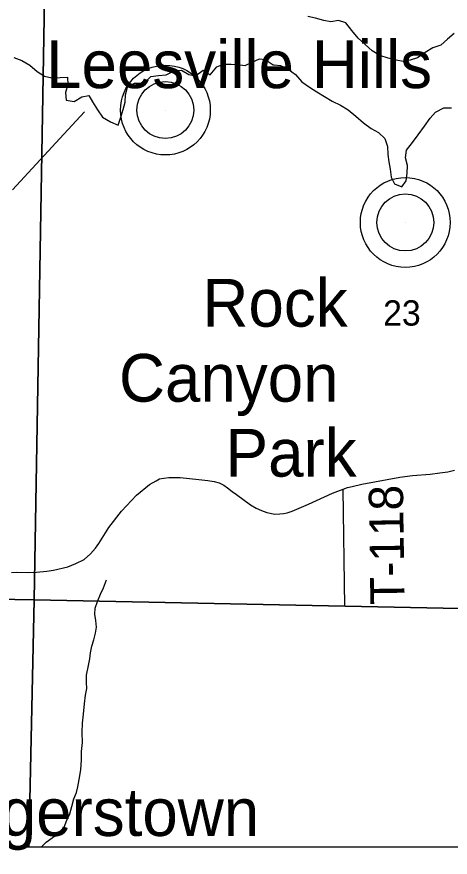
# Model space of a CAD drawing. Extents: x -1.2 to 34, y -8.5 to 22.
# Drawn here: x 7.31 to 8.028, y 18.307 to 19.699 of the extents above; entities that cross this region are included whole.
import ezdxf

# ---------------------------------------------------------------- set-up
doc = ezdxf.new("R2010")
doc.units = 0
for name, color, linetype in [('GM_X_County_Road', 7, 'Continuous'), ('GM_X_Major_Lake', 7, 'Continuous'), ('GM_X_Minor_River', 7, 'Continuous'), ('GM_X_Section', 7, 'Continuous'), ('GM_X_Section_Text', 7, 'Continuous'), ('GM_X_State_Route', 7, 'Continuous'), ('GM_X_Township_Road', 7, 'Continuous'), ('GM_X_Township_Road_Text', 7, 'Continuous'), ('GM_X_Unincorporated', 7, 'Continuous'), ('GM_X_Unincorporated_Location', 7, 'Continuous'), ('GM_X_Unincorporated_Text', 7, 'Continuous'), ('SH_Text', 7, 'Continuous')]:
    doc.layers.add(name, color=color, linetype=linetype)

msp = doc.modelspace()

# ---------------------------------------------------------------- linework, layer by layer
at = {"layer": 'GM_X_County_Road'}
msp.add_line((7.388, 19.5045), (7.4222, 19.5416), dxfattribs=at)
msp.add_lwpolyline([(7.303, 19.4125), (7.388, 19.5045)], dxfattribs=at)
at = {"layer": 'GM_X_Major_Lake'}
for points in [[(8.0348, 19.6713), (8.0239, 19.662), (8.0127, 19.6519), (7.9994, 19.6475), (7.987, 19.6397), (7.9742, 19.6312), (7.9621, 19.6272), (7.9504, 19.6247), (7.9386, 19.6272), (7.9256, 19.6304), (7.9118, 19.6347), (7.8992, 19.6428), (7.8872, 19.6529), (7.8756, 19.6633), (7.8655, 19.6764), (7.8554, 19.6891), (7.8432, 19.6927), (7.8303, 19.6906), (7.8189, 19.6927), (7.8051, 19.6966), (7.7922, 19.6995)], [(7.3052, 19.6314), (7.3182, 19.6263), (7.3316, 19.6186), (7.3439, 19.6082), (7.3559, 19.6004), (7.3681, 19.5976), (7.3817, 19.5985), (7.3939, 19.5987), (7.3945, 19.5866), (7.3909, 19.5737), (7.3919, 19.5608), (7.4048, 19.5587), (7.4176, 19.5665), (7.4294, 19.5686), (7.4356, 19.5581), (7.4435, 19.5446), (7.452, 19.5329), (7.4651, 19.5252), (7.4781, 19.5197), (7.4821, 19.5327), (7.486, 19.5453), (7.4896, 19.5575), (7.4902, 19.5696), (7.4934, 19.5826), (7.5051, 19.5888), (7.5207, 19.5891), (7.5319, 19.6003), (7.5448, 19.6016), (7.5573, 19.603), (7.5716, 19.61), (7.583, 19.6106), (7.5953, 19.6032), (7.6064, 19.6011), (7.6188, 19.6104), (7.6303, 19.6027), (7.6415, 19.6158), (7.6528, 19.6205), (7.6653, 19.6207), (7.6756, 19.6197), (7.6886, 19.6184), (7.6999, 19.6239), (7.712, 19.6291), (7.7215, 19.6281), (7.7346, 19.6192)], [(7.7346, 19.6192), (7.7368, 19.6196), (7.7471, 19.6183), (7.7598, 19.6124), (7.7717, 19.6035), (7.7825, 19.5912), (7.7952, 19.5823), (7.8075, 19.5749), (7.8198, 19.5671), (7.8329, 19.559), (7.8463, 19.5528), (7.8593, 19.545), (7.8717, 19.5346), (7.8848, 19.5231), (7.8971, 19.5142), (7.9094, 19.5072), (7.9202, 19.4975), (7.9242, 19.4843), (7.9252, 19.471), (7.9265, 19.4589), (7.929, 19.4468), (7.9304, 19.4335), (7.9359, 19.4222), (7.9481, 19.4175), (7.9556, 19.4271), (7.9569, 19.4397), (7.9578, 19.4526), (7.9542, 19.4654), (7.9559, 19.478), (7.9659, 19.4907), (7.9752, 19.5037), (7.9856, 19.5179), (7.9949, 19.531), (8.0039, 19.541), (8.0178, 19.5484), (8.0307, 19.5483)]]:
    msp.add_lwpolyline(points, dxfattribs=at)
at = {"layer": 'GM_X_Minor_River'}
for points in [[(7.416, 18.4521), (7.417, 18.4688), (7.4172, 18.4821), (7.4186, 18.4973), (7.4181, 18.514), (7.4187, 18.5292), (7.4198, 18.5391), (7.4208, 18.5497), (7.4219, 18.5615), (7.424, 18.5755), (7.4258, 18.5866), (7.4254, 18.5968), (7.4253, 18.6086), (7.4289, 18.6249), (7.4311, 18.6356), (7.4322, 18.6455), (7.4344, 18.6569), (7.4377, 18.6671), (7.4402, 18.6782), (7.4421, 18.6884), (7.4408, 18.6994), (7.4392, 18.71), (7.4399, 18.7199), (7.4436, 18.731), (7.4488, 18.7431), (7.4537, 18.7534), (7.4585, 18.7664)], [(7.3511, 18.3243), (7.3585, 18.3324), (7.3687, 18.3393), (7.38, 18.3463), (7.3883, 18.357), (7.3931, 18.3684), (7.398, 18.3791), (7.4013, 18.3913), (7.4046, 18.4042), (7.4087, 18.4145), (7.4109, 18.424), (7.4134, 18.4358), (7.416, 18.4521)]]:
    msp.add_lwpolyline(points, dxfattribs=at)
at = {"layer": 'GM_X_Section'}
for points in [[(6.3436, 19.7459), (7.3559, 19.7295), (7.3389, 18.7336), (6.3194, 18.751)], [(8.3845, 19.7092), (8.3694, 18.7126), (7.3389, 18.7336), (7.3559, 19.7295)]]:
    msp.add_lwpolyline(points, close=True, dxfattribs=at)
for points in [[(6.5688, 17.7257), (6.3024, 17.731), (6.3194, 18.751), (7.3389, 18.7336), (7.3297, 18.3243)], [(7.3297, 18.3243), (7.3389, 18.7336), (8.3694, 18.7126), (8.3383, 17.696), (7.3158, 17.711), (7.3184, 17.8243)]]:
    msp.add_lwpolyline(points, dxfattribs=at)
at = {"layer": 'GM_X_State_Route'}
msp.add_lwpolyline([(7.3012, 18.779), (7.3102, 18.7793), (7.3292, 18.779), (7.3428, 18.7792), (7.3598, 18.7807), (7.371, 18.7826), (7.3947, 18.7879), (7.4077, 18.7934), (7.4217, 18.8005), (7.4323, 18.8097), (7.4403, 18.8192), (7.4459, 18.8268), (7.4626, 18.8533), (7.4832, 18.8805), (7.5085, 18.9068), (7.5298, 18.9247), (7.5408, 18.9308), (7.5464, 18.9337), (7.5535, 18.935), (7.562, 18.936), (7.5806, 18.9358), (7.6115, 18.9327), (7.6265, 18.9309), (7.6368, 18.9293), (7.6451, 18.927), (7.6531, 18.9233), (7.6594, 18.9188), (7.6667, 18.9131), (7.674, 18.9077), (7.6972, 18.8909), (7.7068, 18.8852), (7.7156, 18.8814), (7.7244, 18.8782), (7.7378, 18.8756), (7.746, 18.8758), (7.7519, 18.8763), (7.7583, 18.8777), (7.7661, 18.8805), (7.7933, 18.8921), (7.8332, 18.9099), (7.8508, 18.9169), (7.8582, 18.9194), (7.8656, 18.9214), (7.8819, 18.9249), (7.9448, 18.9365), (7.966, 18.9393), (7.9953, 18.9418), (8.0113, 18.9436), (8.0243, 18.9455), (8.0353, 18.9481)], dxfattribs=at)
at = {"layer": 'GM_X_Township_Road'}
msp.add_line((7.8536, 18.7226), (7.8508, 18.9169), dxfattribs=at)
at = {"layer": 'GM_X_Unincorporated'}
for centre, radius in [((7.5562, 19.5445), 0.0744), ((7.5562, 19.5445), 0.0472), ((7.9539, 19.3584), 0.0744), ((7.9539, 19.3584), 0.0472)]:
    msp.add_circle(centre, radius, dxfattribs=at)
at = {"layer": 'GM_X_Unincorporated_Location'}
for p, q in [((7.5562, 19.5445), (7.5562, 19.5445)), ((7.9539, 19.3584), (7.9539, 19.3584))]:
    msp.add_line(p, q, dxfattribs=at)
at = {"layer": 'SH_Text'}
msp.add_lwpolyline([(6.5732, 17.8243), (6.5732, 18.3243), (8.2113, 18.3243), (8.2113, 17.8243), (6.7063, 17.8243)], dxfattribs=at)

# ---------------------------------------------------------------- texts
at = {"layer": 'GM_X_Section_Text'}
msp.add_text('23', height=0.04186, rotation=0, dxfattribs=at).set_placement((7.9172, 19.1876))
at = {"layer": 'GM_X_Township_Road_Text'}
msp.add_text('T-118', height=0.05682, rotation=90.8431, dxfattribs=at).set_placement((7.9529, 18.7256))
at = {"layer": 'GM_X_Unincorporated_Text'}
for s, height, p in [('Leesville Hills', 0.078977, (7.3585, 19.5808)), ('Rock', 0.07898, (7.6176, 19.1858)), ('Canyon', 0.07898, (7.4793, 19.0616)), ('Park', 0.07898, (7.656, 18.9375)), ('New Hagerstown', 0.078977, (6.9076, 18.3425))]:
    msp.add_text(s, height=height, rotation=0, dxfattribs=at).set_placement(p)

doc.saveas('drawing.dxf')
